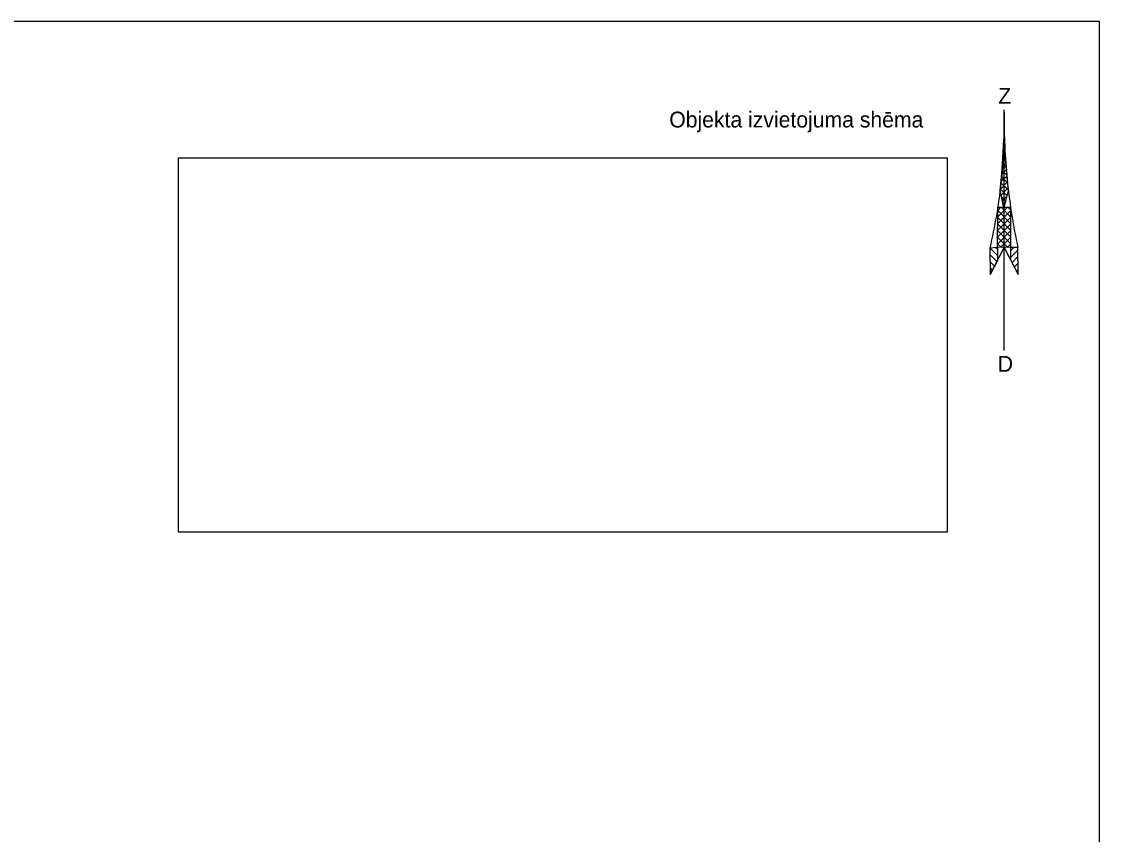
# Model space of a CAD drawing. Extents: x 496127 to 496334, y 303823 to 303967.
# Drawn here: x 496266 to 496334.1, y 303915.5 to 303966.8 of the extents above; entities that cross this region are included whole.
import ezdxf

# ---------------------------------------------------------------- set-up
doc = ezdxf.new("R2010")
doc.units = 0
doc.layers.add('RAMI_PLAN_####_TKST_#', color=7, linetype='Continuous')

msp = doc.modelspace()

# ---------------------------------------------------------------- linework, layer by layer
at = {"layer": 'RAMI_PLAN_####_TKST_#'}
for p, q in [((496334.105, 303966.843), (496138.105, 303966.843)), ((496334.105, 303822.887), (496334.105, 303966.843)), ((496328.073, 303961.276), (496328.073, 303946.074)), ((496328.01, 303958.186), (496328.074, 303959.423)), ((496328.051, 303959.001), (496328.116, 303959.064)), ((496328.074, 303959.423), (496328.096, 303959.424)), ((496328.076, 303959.424), (496328.1, 303959.399)), ((496328.096, 303959.424), (496328.153, 303958.259)), ((496328.03, 303958.556), (496328.134, 303958.661)), ((496328.032, 303958.622), (496328.143, 303958.512)), ((496328.053, 303959.024), (496328.12, 303958.957)), ((496327.938, 303957.24), (496328.01, 303958.186)), ((496327.969, 303957.651), (496328.185, 303957.868)), ((496327.983, 303957.827), (496328.207, 303957.603)), ((496328.002, 303958.107), (496328.153, 303958.259)), ((496328.011, 303958.22), (496328.17, 303958.064)), ((496328.153, 303958.259), (496328.274, 303956.766)), ((496327.823, 303956.196), (496327.938, 303957.24)), ((496327.881, 303956.719), (496328.249, 303957.084)), ((496327.916, 303957.05), (496328.281, 303956.682)), ((496327.933, 303957.19), (496328.216, 303957.475)), ((496327.953, 303957.435), (496328.243, 303957.144)), ((496327.831, 303956.245), (496328.281, 303956.697)), ((496327.875, 303956.667), (496328.332, 303956.209)), ((496328.274, 303956.766), (496328.338, 303956.169)), ((496328.07, 303955.071), (496327.823, 303956.196)), ((496327.835, 303956.286), (496328.263, 303955.859)), ((496327.894, 303955.885), (496328.322, 303956.314)), ((496327.915, 303955.785), (496328.18, 303955.517)), ((496327.969, 303955.541), (496328.254, 303955.825)), ((496328.338, 303956.169), (496328.07, 303955.071)), ((496327.657, 303952.589), (496327.678, 303955.115)), ((496327.673, 303954.497), (496328.292, 303955.115)), ((496327.678, 303955.115), (496328.485, 303955.114)), ((496327.678, 303954.921), (496327.87, 303955.114)), ((496327.891, 303955.115), (496328.487, 303954.522)), ((496328.033, 303955.243), (496328.095, 303955.179)), ((496328.044, 303955.193), (496328.118, 303955.267)), ((496328.313, 303955.114), (496328.485, 303954.945)), ((496328.485, 303955.114), (496328.491, 303952.586)), ((496327.667, 303953.644), (496328.487, 303954.465)), ((496327.67, 303954.069), (496328.485, 303954.888)), ((496327.673, 303954.488), (496328.489, 303953.675)), ((496327.678, 303954.908), (496328.487, 303954.097)), ((496327.658, 303952.793), (496328.489, 303953.622)), ((496327.662, 303953.219), (496328.487, 303954.044)), ((496327.667, 303953.65), (496328.491, 303952.827)), ((496327.67, 303954.069), (496328.489, 303953.251)), ((496327.661, 303953.232), (496328.31, 303952.586)), ((496327.877, 303952.588), (496328.489, 303953.2)), ((496327.173, 303952.553), (496327.657, 303952.589)), ((496327.173, 303952.553), (496327.195, 303950.867)), ((496327.177, 303952.552), (496327.656, 303952.072)), ((496327.195, 303950.867), (496328.086, 303952.576)), ((496327.568, 303952.583), (496327.657, 303952.493)), ((496327.657, 303952.589), (496327.654, 303951.746)), ((496327.657, 303952.815), (496327.885, 303952.587)), ((496328.491, 303952.586), (496327.657, 303952.589)), ((496328.086, 303952.576), (496328.973, 303950.868)), ((496328.295, 303952.587), (496328.49, 303952.778)), ((496328.487, 303951.951), (496328.954, 303952.418)), ((496328.491, 303952.586), (496328.489, 303951.793)), ((496328.49, 303952.375), (496328.693, 303952.582)), ((496328.95, 303952.576), (496328.491, 303952.586)), ((496328.973, 303950.868), (496328.95, 303952.576)), ((496327.179, 303952.125), (496327.622, 303951.686)), ((496327.184, 303951.697), (496327.477, 303951.407)), ((496327.654, 303951.746), (496327.195, 303950.867)), ((496328.489, 303951.793), (496328.973, 303950.868)), ((496328.58, 303951.619), (496328.957, 303951.999)), ((496328.723, 303951.342), (496328.962, 303951.582)), ((496327.192, 303951.27), (496327.332, 303951.13)), ((496327.197, 303950.874), (496327.205, 303950.881)), ((496328.867, 303951.065), (496328.97, 303951.165)), ((496328.973, 303950.87), (496328.973, 303950.87))]:
    msp.add_line(p, q, dxfattribs=at)
for points in [[(496328.073, 303961.274), (496328.079, 303961.016), (496328.084, 303960.758), (496328.086, 303960.499), (496328.087, 303960.241), (496328.085, 303959.983), (496328.082, 303959.724), (496328.076, 303959.465), (496328.068, 303959.207), (496328.059, 303958.948), (496328.047, 303958.689), (496328.034, 303958.431), (496328.018, 303958.172), (496328, 303957.914), (496327.981, 303957.656), (496327.959, 303957.397), (496327.936, 303957.139), (496327.91, 303956.882), (496327.882, 303956.624), (496327.853, 303956.367), (496327.821, 303956.109), (496327.788, 303955.853), (496327.752, 303955.596), (496327.715, 303955.34), (496327.675, 303955.084), (496327.634, 303954.828), (496327.59, 303954.573), (496327.545, 303954.318), (496327.498, 303954.064), (496327.448, 303953.81), (496327.397, 303953.557), (496327.344, 303953.304), (496327.289, 303953.052), (496327.232, 303952.8), (496327.173, 303952.549)], [(496328.073, 303961.274), (496328.071, 303961.017), (496328.071, 303960.759), (496328.073, 303960.502), (496328.076, 303960.244), (496328.081, 303959.987), (496328.088, 303959.729), (496328.096, 303959.472), (496328.106, 303959.214), (496328.117, 303958.957), (496328.131, 303958.699), (496328.146, 303958.442), (496328.162, 303958.184), (496328.181, 303957.927), (496328.201, 303957.67), (496328.222, 303957.413), (496328.246, 303957.156), (496328.271, 303956.899), (496328.298, 303956.642), (496328.326, 303956.386), (496328.356, 303956.13), (496328.388, 303955.874), (496328.421, 303955.618), (496328.456, 303955.362), (496328.493, 303955.107), (496328.531, 303954.852), (496328.571, 303954.597), (496328.613, 303954.343), (496328.656, 303954.089), (496328.701, 303953.835), (496328.748, 303953.582), (496328.796, 303953.329), (496328.846, 303953.077), (496328.897, 303952.824), (496328.95, 303952.573)]]:
    msp.add_lwpolyline(points, dxfattribs=at)
msp.add_lwpolyline([(496275.903, 303934.63), (496324.496, 303934.63), (496324.496, 303958.223), (496275.903, 303958.223)], close=True, dxfattribs=at)

# ---------------------------------------------------------------- texts
for s, p in [('Z', (496327.715, 303961.655)), ('D', (496327.679, 303944.73))]:
    msp.add_text(s, height=1, rotation=359.99874, dxfattribs=at).set_placement(p)
msp.add_text('Objekta izvietojuma shēma', height=1, dxfattribs=at).set_placement((496306.924, 303960.155))

doc.saveas('drawing.dxf')
